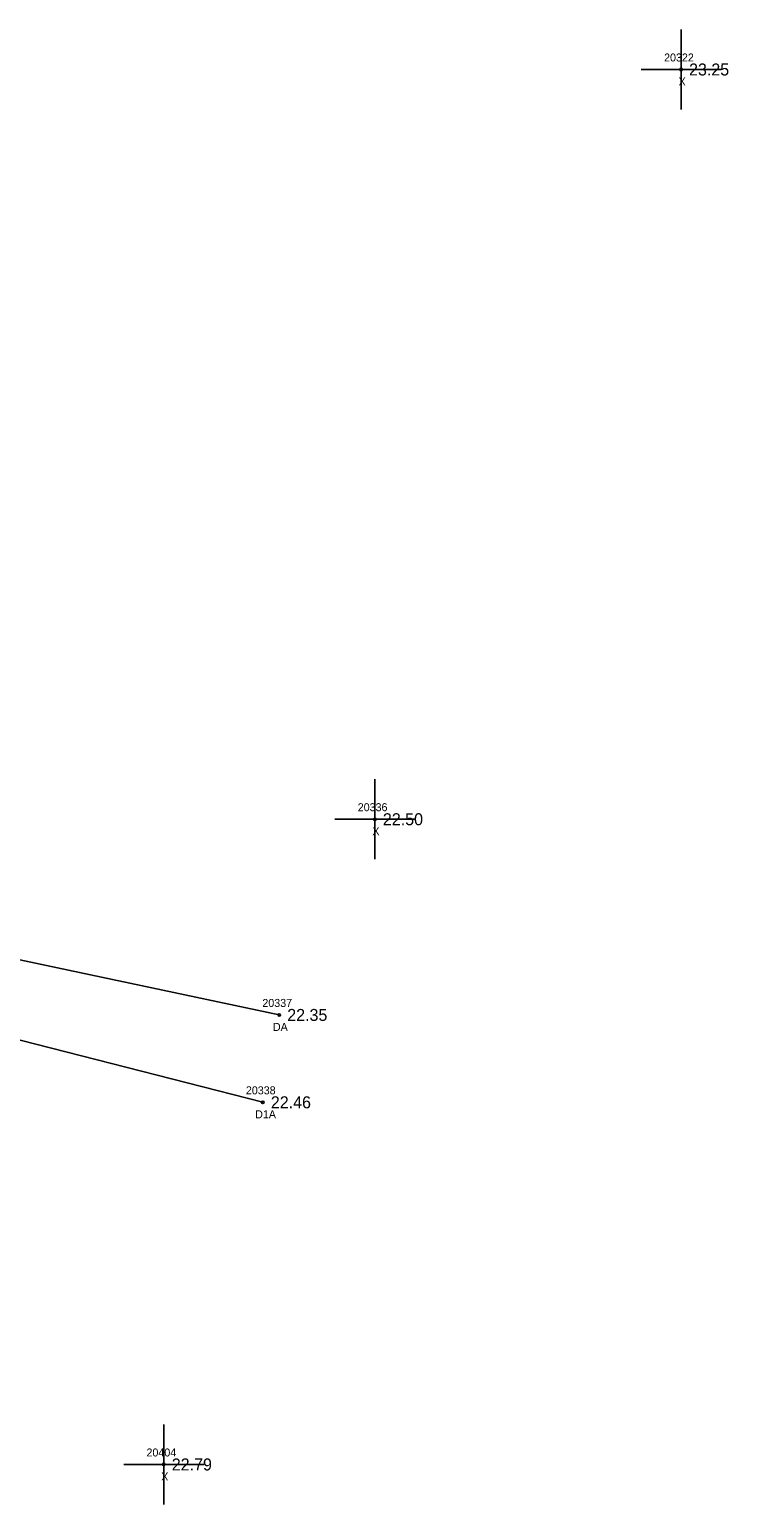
# Model space of a CAD drawing. Extents: x 2655177 to 2656219, y 761780 to 764748.
# Drawn here: x 2655936.8 to 2656024.2, y 763835.2 to 764019.5 of the extents above; entities that cross this region are included whole.
import ezdxf

# ---------------------------------------------------------------- set-up
doc = ezdxf.new("R2010")
doc.units = 0
for name, color, linetype in [('RD_EX_Driveway', 7, 'Continuous'), ('RD_EX_Driveway_txCode', 7, 'Continuous'), ('RD_EX_Misc', 7, 'Continuous'), ('RD_EX_Misc_txCode', 7, 'Continuous'), ('RD_EX_TX_Driveway_ELEV', 7, 'Continuous'), ('RD_EX_TX_Misc_ELEV', 7, 'Continuous'), ('RD_SMD_Locator', 7, 'Continuous')]:
    doc.layers.add(name, color=color, linetype=linetype)

msp = doc.modelspace()

# ---------------------------------------------------------------- linework, layer by layer
at = {"layer": 'RD_EX_Driveway'}
for points in [[(2655968.03, 763896.35), (2655928.45, 763904.73), (2655902.29, 763908.24)], [(2655965.98, 763885.43), (2655928.09, 763895.13), (2655901.11, 763899.02)]]:
    msp.add_lwpolyline(points, dxfattribs=at)
at = {"layer": 'RD_EX_Misc'}
for p, q in [((2656018.28, 764009.51), (2656018.28, 764019.51)), ((2656013.28, 764014.51), (2656023.28, 764014.51)), ((2655979.99, 763915.81), (2655979.99, 763925.81)), ((2655974.99, 763920.81), (2655984.99, 763920.81)), ((2655953.59, 763835.17), (2655953.59, 763845.17)), ((2655948.59, 763840.17), (2655958.59, 763840.17))]:
    msp.add_line(p, q, dxfattribs=at)
at = {"layer": 'RD_SMD_Locator'}
for centre in [(2656018.28, 764014.51), (2655979.99, 763920.81), (2655968.03, 763896.35), (2655965.98, 763885.43), (2655953.59, 763840.17)]:
    msp.add_circle(centre, 0.15, dxfattribs=at)

# ---------------------------------------------------------------- texts
at = {"layer": 'RD_EX_Driveway_txCode'}
for s, p in [('20337', (2655965.92, 763897.35)), ('DA', (2655967.24, 763894.35)), ('20338', (2655963.86, 763886.43)), ('D1A', (2655965.02, 763883.43))]:
    msp.add_text(s, height=1, dxfattribs=at).set_placement(p)
at = {"layer": 'RD_EX_Misc_txCode'}
for s, p in [('20322', (2656016.16, 764015.51)), ('X', (2656017.97, 764012.51)), ('20336', (2655977.85, 763921.81)), ('X', (2655979.68, 763918.81)), ('20404', (2655951.43, 763841.17)), ('X', (2655953.27, 763838.17))]:
    msp.add_text(s, height=1, dxfattribs=at).set_placement(p)
at = {"layer": 'RD_EX_TX_Driveway_ELEV'}
for s, p in [('22.35', (2655969.03, 763895.6)), ('22.46', (2655966.98, 763884.68))]:
    msp.add_text(s, height=1.5, dxfattribs=at).set_placement(p)
at = {"layer": 'RD_EX_TX_Misc_ELEV'}
for s, p in [('23.25', (2656019.28, 764013.76)), ('22.50', (2655980.99, 763920.06)), ('22.79', (2655954.59, 763839.42))]:
    msp.add_text(s, height=1.5, dxfattribs=at).set_placement(p)

doc.saveas('drawing.dxf')
